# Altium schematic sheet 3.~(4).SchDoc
size 420 x 297 mm
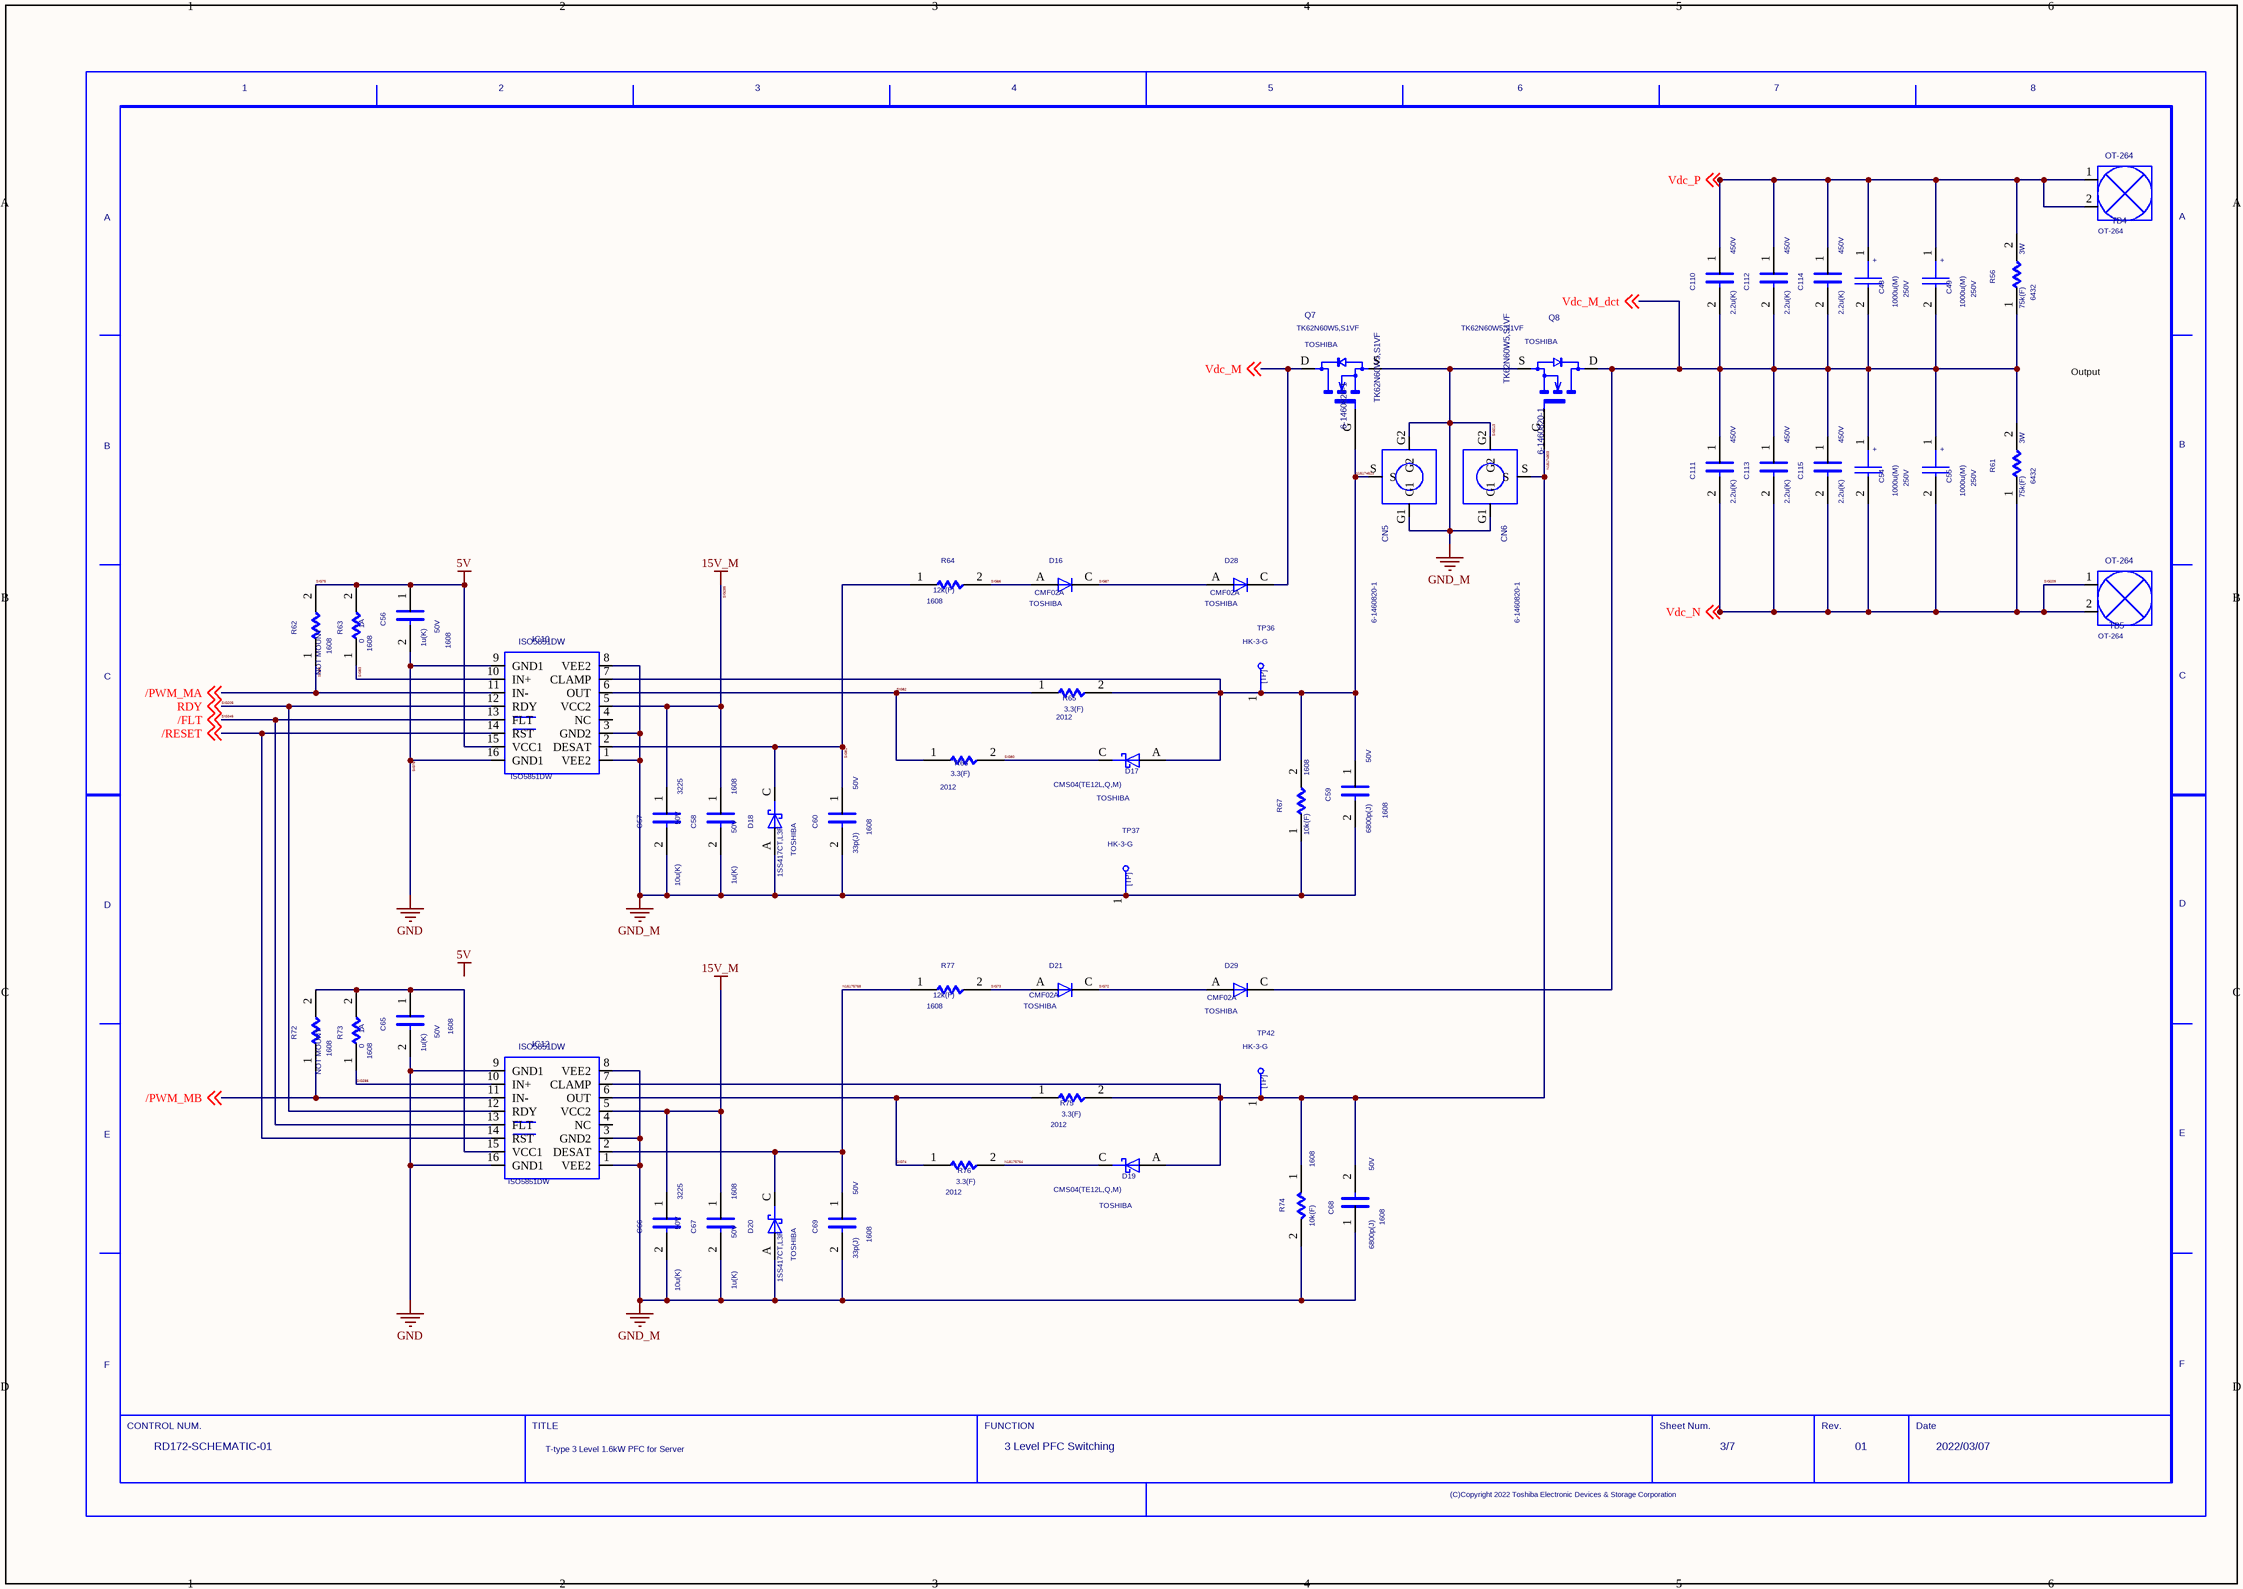
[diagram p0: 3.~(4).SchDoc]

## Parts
C48  VAL2: 250V  VAL1: 1000u(M)  (hidden comment: CP)
C49  VAL2: 250V  VAL1: 1000u(M)  (hidden comment: CP)
C54  VAL2: 250V  VAL1: 1000u(M)  (hidden comment: CP)
C55  VAL2: 250V  VAL1: 1000u(M)  (hidden comment: CP)
C56  SIZECODESMD: 1608  VAL2: 50V  VAL1: 1u(K)  (hidden comment: C)
C57  SIZECODESMD: 3225  VAL2: 50V  VAL1: 10u(K)  (hidden comment: C)
C58  SIZECODESMD: 1608  VAL2: 50V  VAL1: 1u(K)  (hidden comment: C)
C59  SIZECODESMD: 1608  VAL2: 50V  VAL1: 6800p(J)  (hidden comment: C)
C60  SIZECODESMD: 1608  VAL2: 50V  VAL1: 33p(J)  (hidden comment: C)
C65  SIZECODESMD: 1608  VAL2: 50V  VAL1: 1u(K)  (hidden comment: C)
C66  SIZECODESMD: 3225  VAL2: 50V  VAL1: 10u(K)  (hidden comment: C)
C67  SIZECODESMD: 1608  VAL2: 50V  VAL1: 1u(K)  (hidden comment: C)
C68  SIZECODESMD: 1608  VAL2: 50V  VAL1: 6800p(J)  (hidden comment: C)
C69  SIZECODESMD: 1608  VAL2: 50V  VAL1: 33p(J)  (hidden comment: C)
C110  VAL2: 450V  VAL1: 2.2u(K)  (hidden comment: C)
C111  VAL2: 450V  VAL1: 2.2u(K)  (hidden comment: C)
C112  VAL2: 450V  VAL1: 2.2u(K)  (hidden comment: C)
C113  VAL2: 450V  VAL1: 2.2u(K)  (hidden comment: C)
C114  VAL2: 450V  VAL1: 2.2u(K)  (hidden comment: C)
C115  VAL2: 450V  VAL1: 2.2u(K)  (hidden comment: C)
CN5  6-1460820-1
CN6  6-1460820-1
D16  USERCOMPTEXT3: TOSHIBA  VAL3: CMF02A  (hidden comment: D)
D17  VAL3: CMS04(TE12L,Q,M)  USERCOMPTEXT3: TOSHIBA  (hidden comment: SBD)
D18  VAL3: 1SS417CT,L3F  USERCOMPTEXT3: TOSHIBA  (hidden comment: SBD)
D19  VAL3: CMS04(TE12L,Q,M)  USERCOMPTEXT3: TOSHIBA  (hidden comment: SBD)
D20  VAL3: 1SS417CT,L3F  USERCOMPTEXT3: TOSHIBA  (hidden comment: SBD)
D21  USERCOMPTEXT3: TOSHIBA  VAL3: CMF02A  (hidden comment: D)
D28  USERCOMPTEXT3: TOSHIBA  VAL3: CMF02A  (hidden comment: D)
D29  USERCOMPTEXT3: TOSHIBA  VAL3: CMF02A  (hidden comment: D)
IC10  ISO5851DW
IC12  ISO5851DW
Q7  TK62N60W5,S1VF  USERCOMPTEXT3: TOSHIBA
Q8  TK62N60W5,S1VF  USERCOMPTEXT3: TOSHIBA
R56  SIZECODESMD: 6432  VAL2: 3W  VAL1: 75k(F)  (hidden comment: R)
R61  SIZECODESMD: 6432  VAL2: 3W  VAL1: 75k(F)  (hidden comment: R)
R62  SIZECODESMD: 1608  NOTMOUNT: NOT MOUNT  (hidden comment: R)
R63  SIZECODESMD: 1608  VAL2: 1A  VAL1: 0  (hidden comment: R)
R64  SIZECODESMD: 1608  VAL1: 12k(F)  (hidden comment: R)
R65  SIZECODESMD: 2012  VAL1: 3.3(F)  (hidden comment: R)
R66  SIZECODESMD: 2012  VAL1: 3.3(F)  (hidden comment: R)
R67  SIZECODESMD: 1608  VAL1: 10k(F)  (hidden comment: R)
R72  SIZECODESMD: 1608  NOTMOUNT: NOT MOUNT  (hidden comment: R)
R73  SIZECODESMD: 1608  VAL2: 1A  VAL1: 0  (hidden comment: R)
R74  SIZECODESMD: 1608  VAL1: 10k(F)  (hidden comment: R)
R75  SIZECODESMD: 2012  VAL1: 3.3(F)  (hidden comment: R)
R76  SIZECODESMD: 2012  VAL1: 3.3(F)  (hidden comment: R)
R77  SIZECODESMD: 1608  VAL1: 12k(F)  (hidden comment: R)
TB4  OT-264
TB5  OT-264
TP36  VAL3: HK-3-G  (hidden comment: TP)
TP37  VAL3: HK-3-G  (hidden comment: TP)
TP42  VAL3: HK-3-G  (hidden comment: TP)
U?  DATE: 2022/03/07  REVISION: 01  SHEETNUMBER: 3/7  FUNCTION: 3 Level PFC Switching  TITLE: T-type 3 Level 1.6kW PFC for Server  DRAWINGNUMBER: RD172-SCHEMATIC-01  (hidden comment: WAKU_DEF100)

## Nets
SIG75: C56.1 IC10.15(VCC1) R62.2 R63.2  [also labelled 5V]
SIG78: C56.2 C65.2 IC10.9(GND1) IC10.16(GND1) IC12.9(GND1) IC12.16(GND1)  [also labelled GND]
SIG213: C57.2 C58.2 C59.2 C60.2 C66.2 C67.2 C68.1 C69.2 CN5.G1 CN5.G2 CN6.G1 CN6.G2 D18.A D20.A IC10.1(VEE2) IC10.3(GND2) IC10.8(VEE2) IC12.1(VEE2) IC12.3(GND2) IC12.8(VEE2) Q7.S Q8.S R67.1 R74.2 TP37.1  [also labelled GND_M]
SIG285: C57.1 C58.1 C66.1 C67.1 IC10.5(VCC2) IC12.5(VCC2)  [also labelled 15V_M]
/PWM_MB: IC12.11(IN-) R72.1 ; off-sheet /PWM_MB
/RESET: IC10.14(RST) IC12.14(RST) ; off-sheet /RESET
N18174803: C68.2 CN6.S D19.A IC12.7(CLAMP) Q8.G R74.1 R75.2 TP42.1
N18174813: C59.1 CN5.S D17.A IC10.7(CLAMP) Q7.G R65.2 R67.2 TP36.1
N18175764: D19.C R76.2
N18175788: C69.1 D20.C IC12.2(DESAT) R77.1
SIG72: D21.C D29.A
SIG73: D21.A R77.2
SIG74: IC12.6(OUT) R75.1 R76.1
SIG80: D17.C R66.2
SIG81: C60.1 D18.C IC10.2(DESAT) R64.1
SIG82: IC10.6(OUT) R65.1 R66.1
SIG83: IC10.10(IN+) R63.1
SIG84: IC10.11(IN-) R62.1 ; off-sheet /PWM_MA  [also labelled /PWM_MA]
SIG86: D16.A R64.2
SIG87: D16.C D28.A
SIG205: IC10.12(RDY) IC12.12(RDY) ; off-sheet RDY  [also labelled RDY]
SIG209: C54.2 C55.2 C111.2 C113.2 C115.2 R61.1 TB5.1 TB5.2 ; off-sheet Vdc_N  [also labelled Vdc_N]
SIG286: IC12.10(IN+) R73.1
SIG345: IC10.13(FLT) IC12.13(FLT) ; off-sheet /FLT  [also labelled /FLT]
Vdc_M: D28.C Q7.D ; off-sheet Vdc_M
Vdc_M_dct: C48.2 C49.2 C54.1 C55.1 C110.2 C111.1 C112.2 C113.1 C114.2 C115.1 D29.C Q8.D R56.1 R61.2 ; off-sheet Vdc_M_dct
Vdc_P: C48.1 C49.1 C110.1 C112.1 C114.1 R56.2 TB4.1 TB4.2 ; off-sheet Vdc_P
NetC65_1: C65.1 IC12.15(VCC1) R72.2 R73.2

Not connected (* = marked no-connect by the designer): IC10 4(NC); IC12 4(NC)

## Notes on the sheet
- Output
  DC380V
- Labels drawn without touching a wire or pin: 5V

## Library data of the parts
C48 C49 C54 C55 = CP: SAVEAREA0: -1450,-153,20294,13055; SAVECOUNT: 52; TIME: 15:02:55; UPDATEUSER: fukuda-y; UPDATETIME: 16:13:42; OriginalSymbolOrigin: (2540,10160); COMP: -C-LGW2E102MELC35
C56 C58 C65 C67 = C: OriginalSymbolOrigin: (2540,7620); COMP: -C-UMK107AB7105KA-T
C57 C66 = C: OriginalSymbolOrigin: (2540,7620); COMP: -C-UMK325AB7106KM-T
C59 C68 = C: OriginalSymbolOrigin: (2540,7620); COMP: -C-GRM1885C1H682JA01D
C60 C69 = C: OriginalSymbolOrigin: (2540,7620); COMP: -C-CGA3E2C0G1H330J080AA
C110-C115 = C: OriginalSymbolOrigin: (2540,7620); COMP: -C-C5750X6S2W225K250KA
CN5 CN6 = 6_1460820_1: MMCX Connector, 170V; MANUFACTURER: TE Connectivity; COMP: -CN-6-1460820-1; TIME: 16:53:54; UPDATEUSER: t5459927; UPDATETIME: 16:17:04; SAVECOUNT: 3; SAVEAREA0: -4427,-12981,14210,683; OriginalSymbolOrigin: (0,0)
D16 D21 D28 D29 = D: SAVEAREA0: -225,-91,12804,7836; SAVECOUNT: 3; TIME: 14:49:55; UPDATEUSER: 19870035; UPDATETIME: 14:20:16; OriginalSymbolOrigin: (5080,5080); COMP: -D-CMF05_AC
D17 D19 = SBD: SAVEAREA0: -4630,-153,17114,13055; TIME: 14:49:55; UPDATEUSER: fukuda-y; UPDATETIME: 08:16:22; SAVECOUNT: 9; OriginalSymbolOrigin: (5080,5080); COMP: -D-CMS04_TE12L_Q_AC
D18 D20 = SBD: SAVEAREA0: -4630,-153,17114,13055; TIME: 14:49:55; UPDATEUSER: fukuda-y; UPDATETIME: 08:16:22; SAVECOUNT: 9; OriginalSymbolOrigin: (5080,5080); COMP: -D-1SS417CTL3F_AC
IC10 IC12 = ISO5851DW: Gate Driver; MANUFACTURER: Txsas Instruments; COMP: -IC-ISO5851DWR; TIME: 16:53:55; UPDATEUSER: t5459927; UPDATETIME: 16:13:36; SAVECOUNT: 2; SAVEAREA0: -16530,-29444,33798,7453; OriginalSymbolOrigin: (0,0)
Q7 = TK62N60W5,S1VF: Nch MOSFET; COMP: -Q-TK62N60W5; NOTE: 600V 61.8A; TIME: 16:53:55; UPDATEUSER: t5459927; SAVECOUNT: 1; OriginalSymbolOrigin: (0,0); INSTANCENAME: INS18652567
Q8 = TK62N60W5,S1VF: Nch MOSFET; COMP: -Q-TK62N60W5; NOTE: 600V 61.8A; TIME: 16:53:55; UPDATEUSER: t5459927; SAVECOUNT: 1; OriginalSymbolOrigin: (0,0); INSTANCENAME: INS18652910
R56 R61 = R: OriginalSymbolOrigin: (5080,5080); COMP: -R-352227KFT
R62 R72 = R: OriginalSymbolOrigin: (5080,5080); COMP: -R-NC_R1608
R63 R73 = R: OriginalSymbolOrigin: (5080,5080); COMP: -R-RK73Z1JTTD
R64 R77 = R: OriginalSymbolOrigin: (5080,5080); COMP: -R-ERJ3EKF1202V; VAL2: 100mW
R65 R66 R75 R76 = R: OriginalSymbolOrigin: (5080,5080); COMP: -R-ERJ6DQF3R3V; VAL2: 500mW
R67 R74 = R: OriginalSymbolOrigin: (5080,5080); COMP: -R-ERJ3EKF1002V; VAL2: 100mW
TB4 = OT_264: Terminal, 50A, M4; MANUFACTURER: Osada; COMP: -TB-OT-264; TIME: 16:53:54; UPDATEUSER: t5459927; SAVECOUNT: 1; SAVEAREA0: -3825,-10384,11084,546; OriginalSymbolOrigin: (0,0); REFERENCE TEMPLATE: TB; INSTANCENAME: INS18174423
TB5 = OT_264: Terminal, 50A, M4; MANUFACTURER: Osada; COMP: -TB-OT-264; TIME: 16:53:54; UPDATEUSER: t5459927; SAVECOUNT: 1; SAVEAREA0: -3825,-10384,11084,546; OriginalSymbolOrigin: (0,0); REFERENCE TEMPLATE: TB; INSTANCENAME: INS18174903
TP36 TP37 TP42 = TP: TIME: 16:12:21; UPDATEUSER: fukuda-y; UPDATETIME: 16:18:11; SAVECOUNT: 2; SAVEAREA0: -242,-92,12810,7836; OriginalSymbolOrigin: (0,7620); COMP: -TP-HK-3-G
U? = WAKU_DEF100: PLOTTIME: HH:MM; SAVEAREA0: 148187,-66180,486823,89919; TIME: 14:30:25; UPDATEUSER: t5459927; UPDATETIME: 09:34:24; SAVECOUNT: 6; OriginalSymbolOrigin: (10160,284480)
